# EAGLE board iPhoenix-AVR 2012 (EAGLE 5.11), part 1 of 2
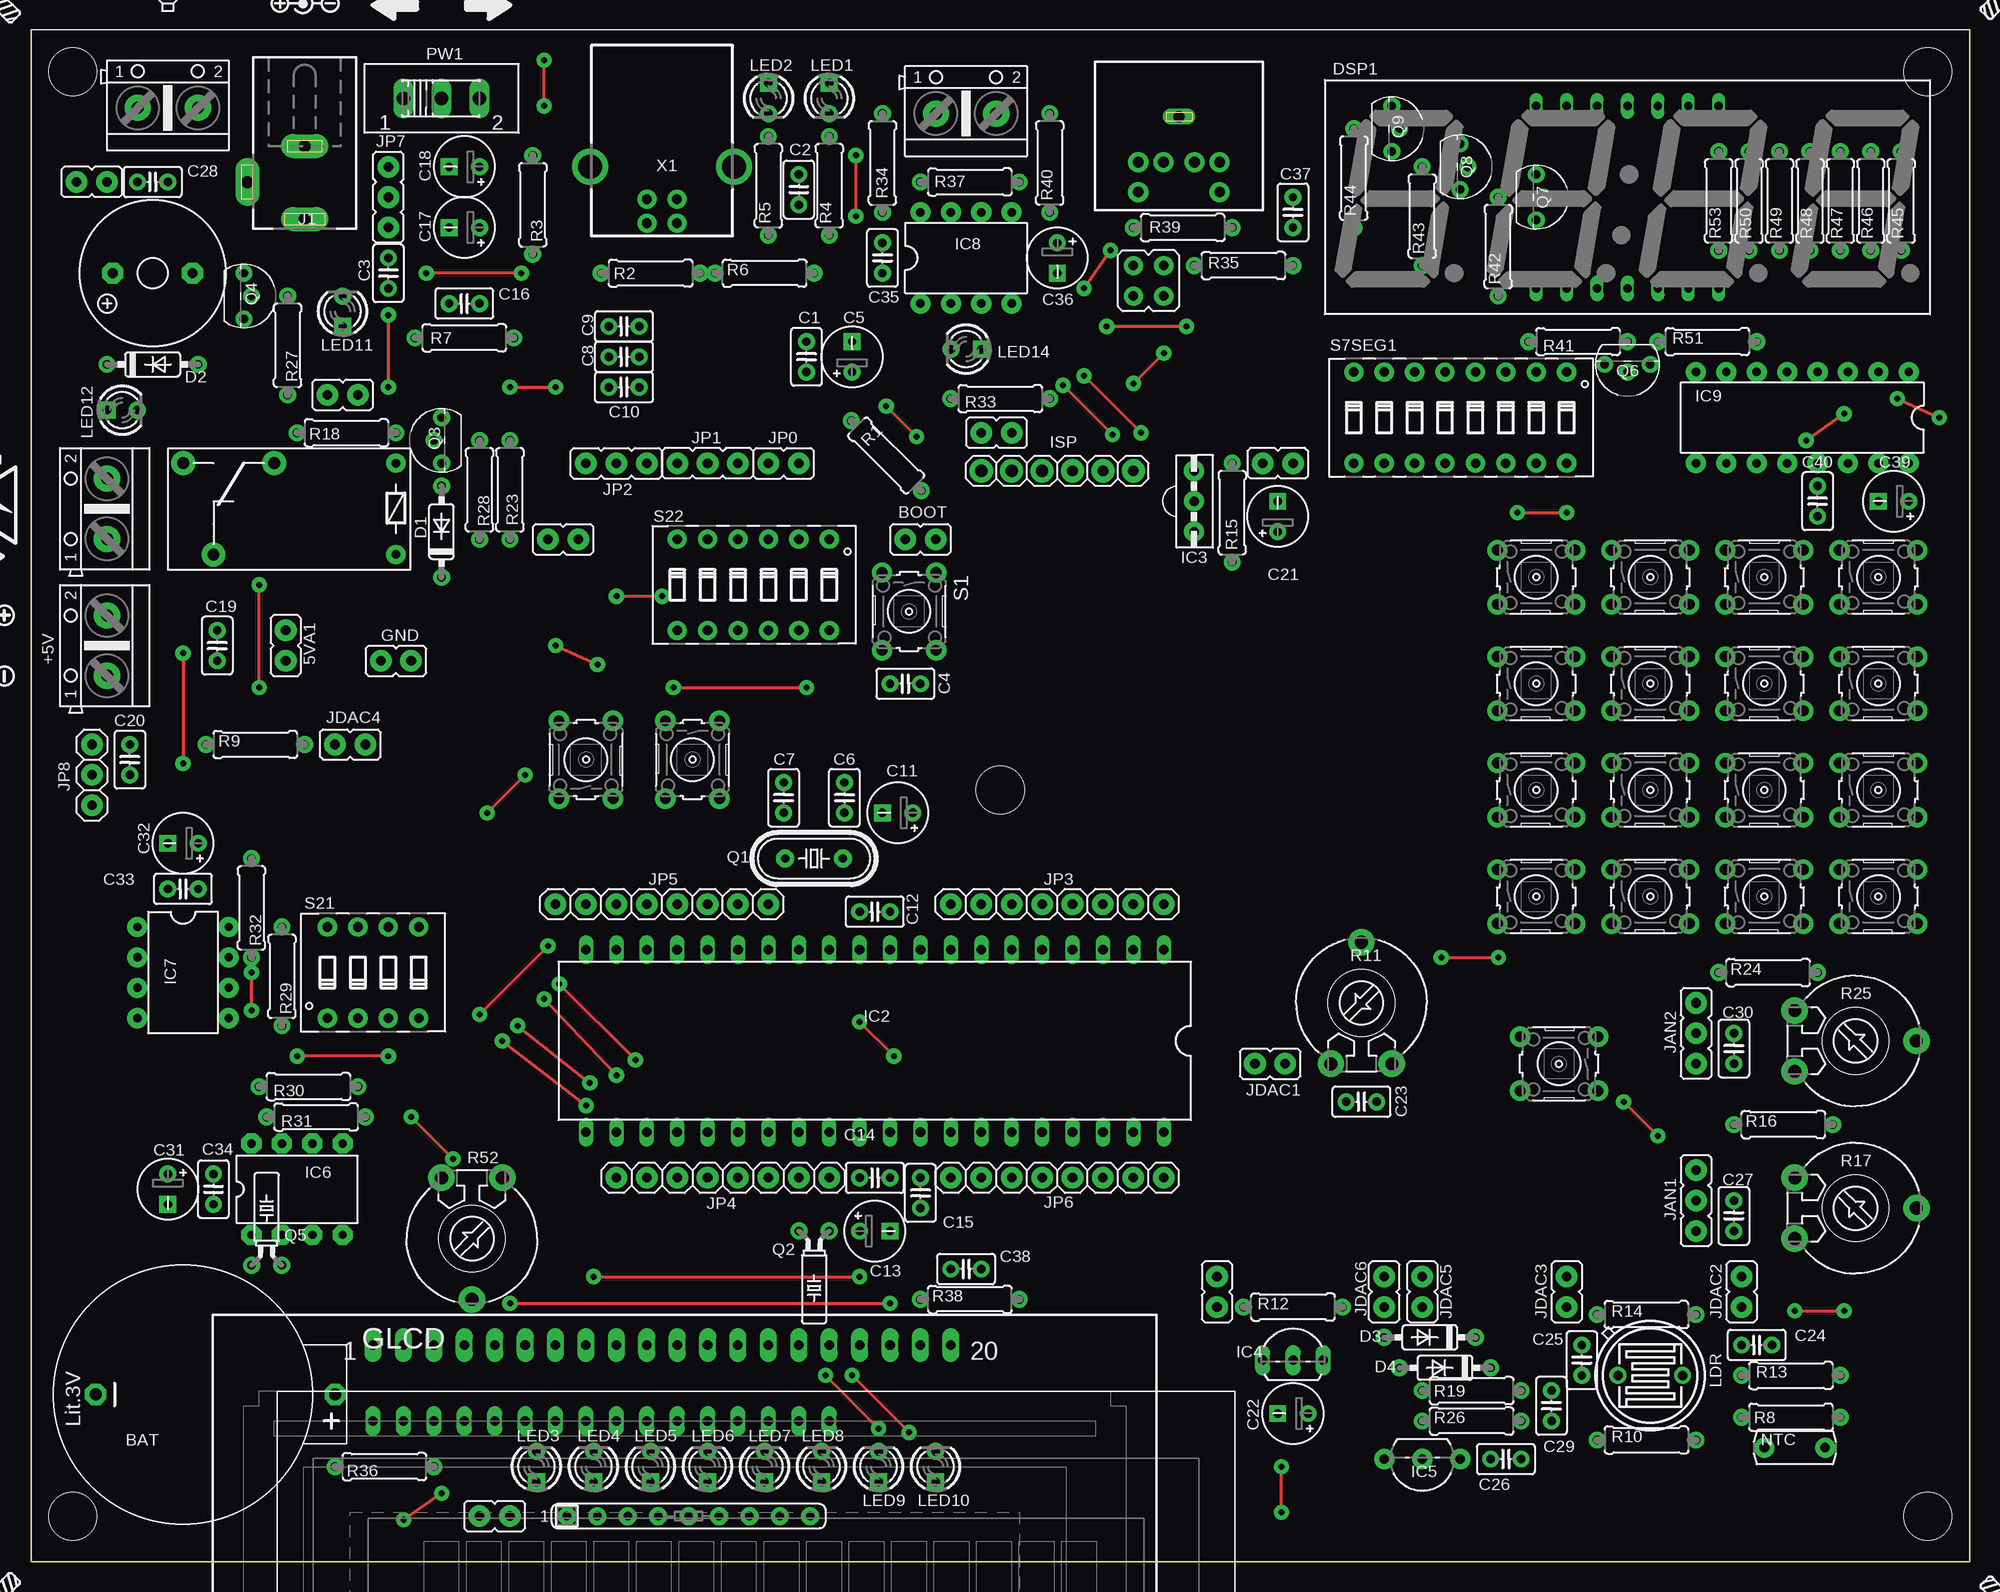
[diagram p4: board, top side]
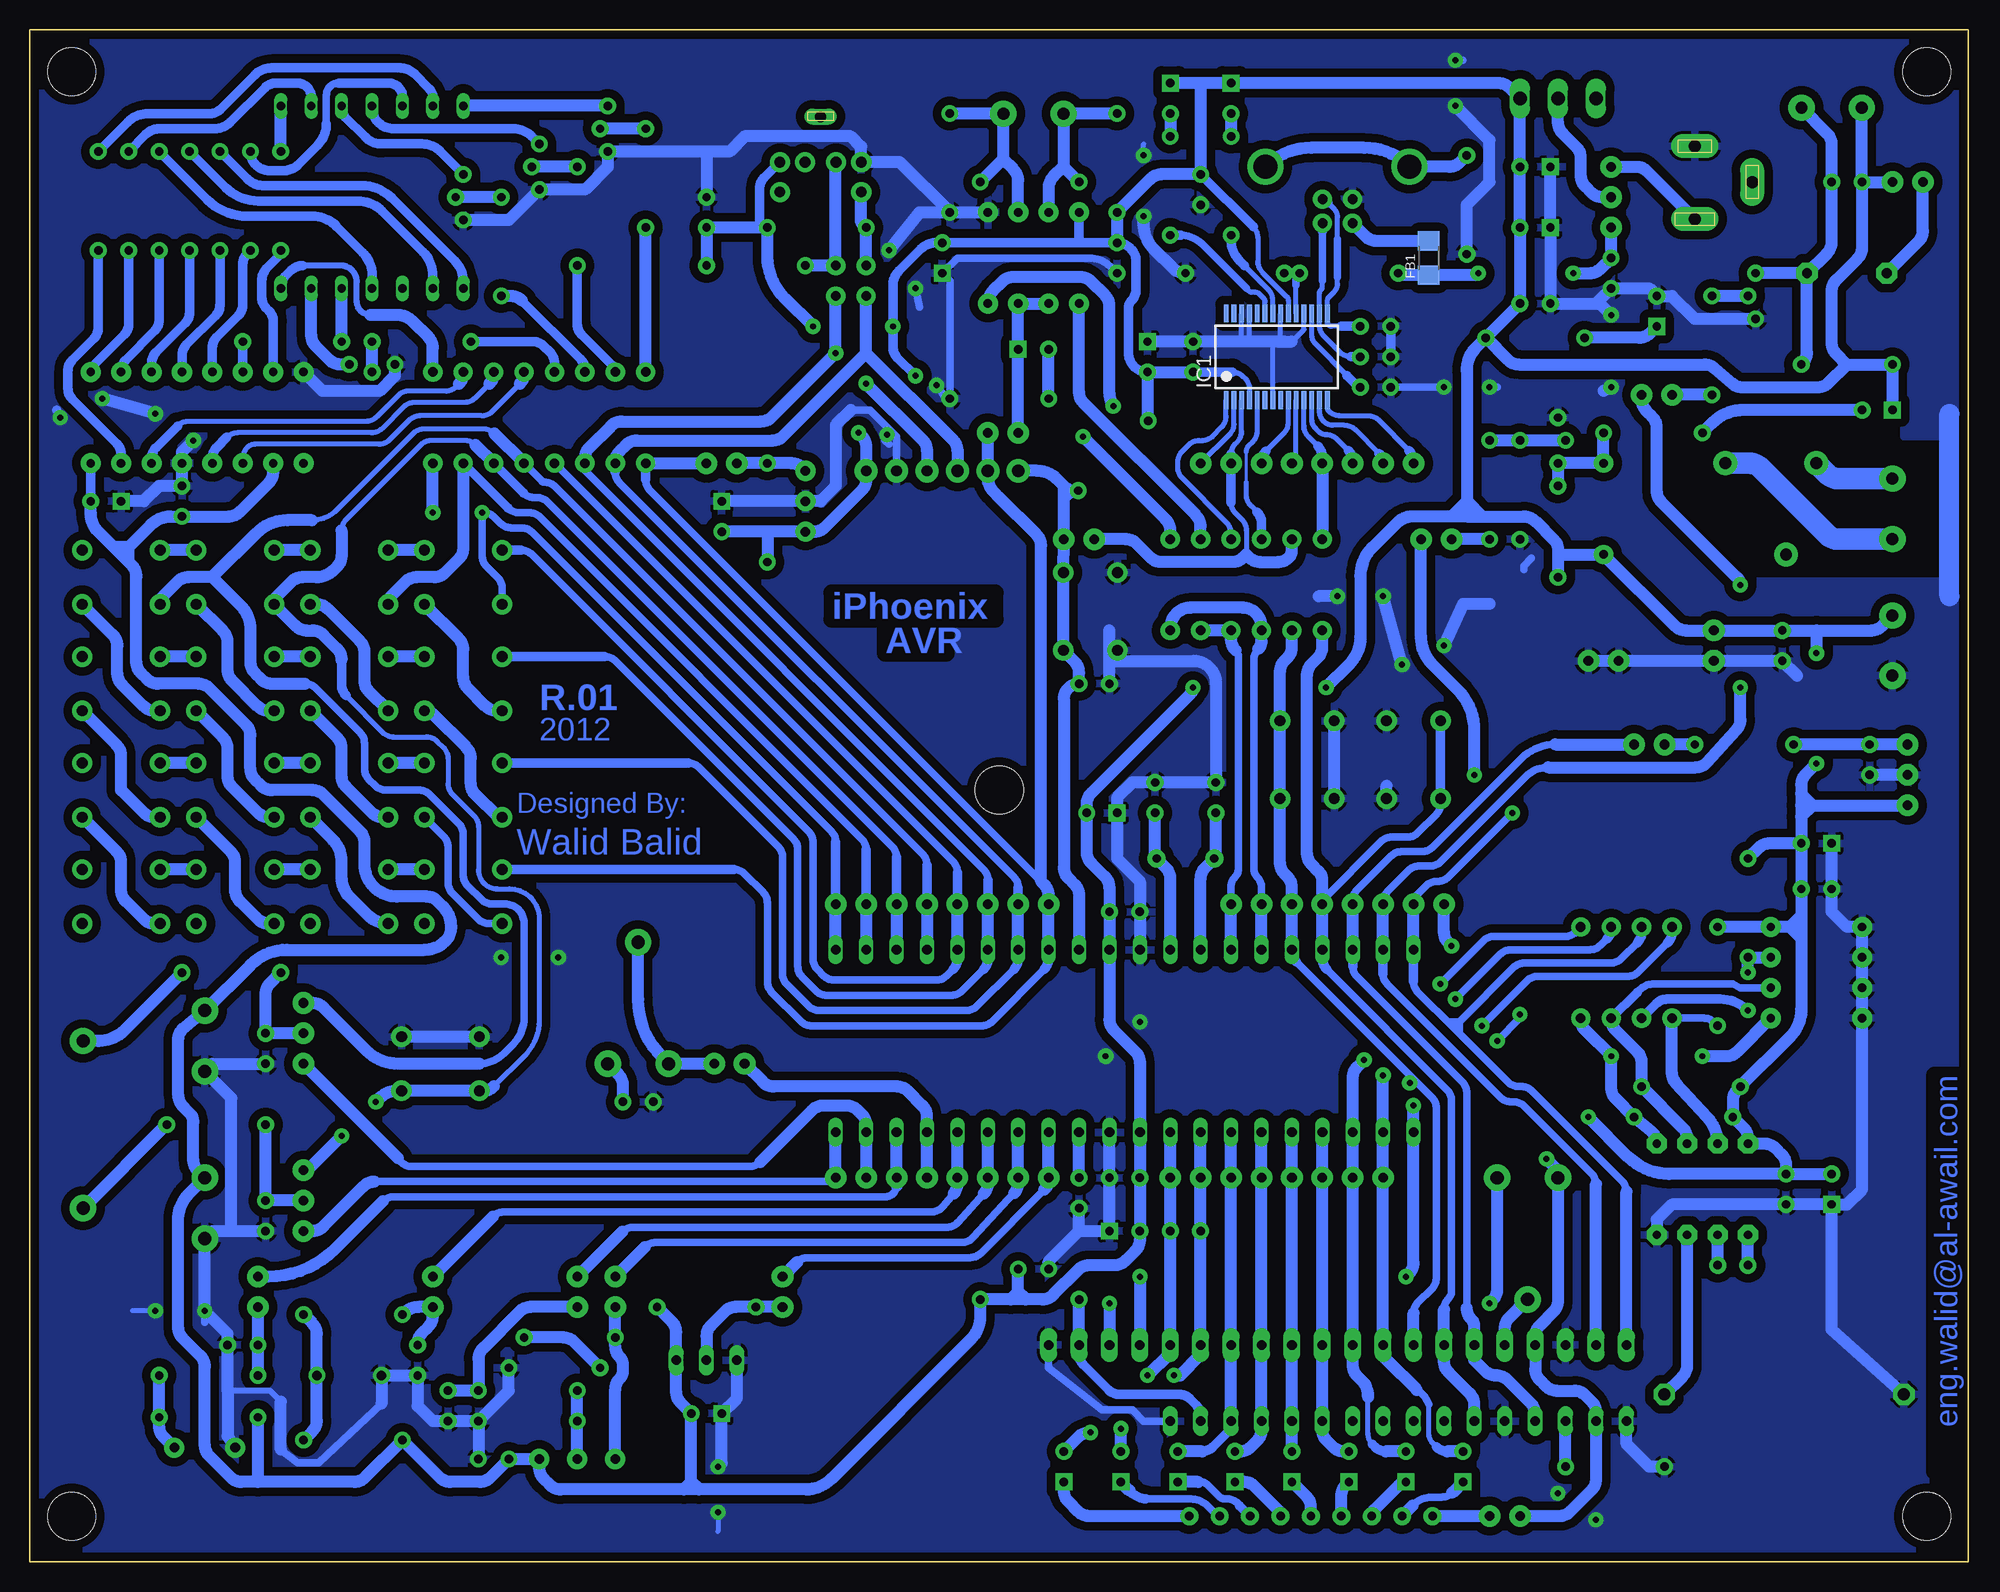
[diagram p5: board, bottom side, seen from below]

Size 161.92 x 127.95 mm. Coordinates in mm from the lower left corner, seen from the top.
Outline: 0,0 0,127.95 161.92,127.95 161.92,0 0,0
Copper layers (1*16): Top 0.035mm / dielectric 1.5mm / Bottom 0.035mm
Design rules "DVK2011 *": minimum track width 16mil, minimum drill 0.5mm, track to track 12mil, track to pad 12mil, pad to pad 12mil, via to via 12mil, smd to smd 12mil, copper to edge 1mil, drill to drill 12mil, minimum pad ring 8mil, minimum via ring 8mil, stop-mask expansion 4mil, vias tented up to drill 0.5mm, thermal gap 10mil
Holes 4 mm at 3.49,3.81 158.43,3.81 3.49,124.46 158.43,124.46 80.96,64.45

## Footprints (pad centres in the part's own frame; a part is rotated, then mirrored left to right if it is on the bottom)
JP1 = drill 0.8 pad 1.8 round: 1 0,-1.27; 2 0,1.27
AK500/2 = drill 1 pad 2.184 round: 1 -2.515,0; 2 2.515,0
BATT = drill 1 pad 1.778 octagon: + 0,10.16; - 0,-9.842
C025-025X050 = drill 0.7 pad 1.4 round: 1 -1.27,0; 2 1.27,0
E2,5-5 = drill 0.7 pad 1.4 round: + -1.27,0 | drill 0.7 pad 1.4 square: - 1.27,0
DO35-7 = drill 0.7 pad 1.4 round: A 3.81,0; C -3.81,0
F512SRWBT14 = drill 0.7 long: 1 -7.62,-6.35; 2 -5.08,-6.35; 3 -2.54,-6.35; 4 0,-6.35; 5 2.54,-6.35; 6 5.08,-6.35; 7 7.62,-6.35; 8 7.62,8.89; 9 5.08,8.89; 10 2.54,8.89; 11 0,8.89; 12 -2.54,8.89; 13 -5.08,8.89; 14 -7.62,8.89
R1206 = smd 1.6 x 1.803: 1 -1.422,0; 2 1.422,0
GDM12864B = drill 0.8 pad 1.422 long: 1 -26.034,33.019; 2 -23.494,33.019; 3 -20.954,33.019; 4 -18.414,33.019; 5 -15.874,33.019; 6 -13.334,33.019; 7 -10.794,33.019; 8 -8.254,33.019; 9 -5.714,33.019; 10 -3.174,33.019; 11 -0.634,33.019; 12 1.906,33.019; 13 4.446,33.019; 14 6.986,33.019; 15 9.526,33.019; 16 12.066,33.019; 17 14.606,33.019; 18 17.146,33.019; 19 19.686,33.019; 20 22.226,33.019
SSOP28 = smd 0.4 x 1.5: 1 -4.225,-3.625; 2 -3.575,-3.625; 3 -2.925,-3.625; 4 -2.275,-3.625; 5 -1.625,-3.625; 6 -0.975,-3.625; 7 -0.325,-3.625; 8 0.325,-3.625; 9 0.975,-3.625; 10 1.625,-3.625; 11 2.275,-3.625; 12 2.925,-3.625; 13 3.575,-3.625; 14 4.225,-3.625; 15 4.225,3.625; 16 3.575,3.625; 17 2.925,3.625; 18 2.275,3.625; 19 1.625,3.625; 20 0.975,3.625; 21 0.325,3.625; 22 -0.325,3.625; 23 -0.975,3.625; 24 -1.625,3.625; 25 -2.275,3.625; 26 -2.925,3.625; 27 -3.575,3.625; 28 -4.225,3.625
DIL40 = drill 0.813 long: 1 -24.13,-7.62; 2 -21.59,-7.62; 3 -19.05,-7.62; 4 -16.51,-7.62; 5 -13.97,-7.62; 6 -11.43,-7.62; 7 -8.89,-7.62; 8 -6.35,-7.62; 9 -3.81,-7.62; 10 -1.27,-7.62; 11 1.27,-7.62; 12 3.81,-7.62; 13 6.35,-7.62; 14 8.89,-7.62; 15 11.43,-7.62; 16 13.97,-7.62; 17 16.51,-7.62; 18 19.05,-7.62; 19 21.59,-7.62; 20 24.13,-7.62; 21 24.13,7.62; 22 21.59,7.62; 23 19.05,7.62; 24 16.51,7.62; 25 13.97,7.62; 26 11.43,7.62; 27 8.89,7.62; 28 6.35,7.62; 29 3.81,7.62; 30 1.27,7.62; 31 -1.27,7.62; 32 -3.81,7.62; 33 -6.35,7.62; 34 -8.89,7.62; 35 -11.43,7.62; 36 -13.97,7.62; 37 -16.51,7.62; 38 -19.05,7.62; 39 -21.59,7.62; 40 -24.13,7.62
IR-RECEIVER = drill 0.8 pad 1.676 round: GND 0,0; OUT 2.54,0; VCC -2.54,0
TO92L = drill 0.8 pad 1.27 long: 1 2.54,0; 2 0,0; 3 -2.54,0
LM35 = drill 0.8 pad 1.676 round: 1 3.175,0; 2 0,0; 3 -3.175,0
DIL8O = drill 0.7 pad 1.676 octagon: 1 -3.81,-3.81; 2 -1.27,-3.81; 3 1.27,-3.81; 4 3.81,-3.81; 5 3.81,3.81; 6 1.27,3.81; 7 -1.27,3.81; 8 -3.81,3.81
DIL8R = drill 0.7 pad 1.676 round: 1 -3.81,-3.81; 2 -1.27,-3.81; 3 1.27,-3.81; 4 3.81,-3.81; 5 3.81,3.81; 6 1.27,3.81; 7 -1.27,3.81; 8 -3.81,3.81
DIL16R = drill 0.7 pad 1.676 round: 1 -8.89,-3.81; 2 -6.35,-3.81; 3 -3.81,-3.81; 4 -1.27,-3.81; 5 1.27,-3.81; 6 3.81,-3.81; 7 6.35,-3.81; 8 8.89,-3.81; 9 8.89,3.81; 10 6.35,3.81; 11 3.81,3.81; 12 1.27,3.81; 13 -1.27,3.81; 14 -3.81,3.81; 15 -6.35,3.81; 16 -8.89,3.81
1X06 = drill 0.9 pad 1.93 round: 1 -6.35,0; 2 -3.81,0; 3 -1.27,0 | drill 1.016 pad 1.93 round: 4 1.27,0; 5 3.81,0; 6 6.35,0
DCJ0202 = drill 1 pad 2 long: 1 0,3.1; 2 4.8,0; 3 0,-3
JP2 = drill 0.8 pad 1.8 round: 1 -2.54,0; 2 0,0; 3 2.54,0
1X08 = drill 0.8 pad 1.8 round: 1 -8.89,0; 2 -6.35,0; 3 -3.81,0; 4 -1.27,0; 5 1.27,0; 6 3.81,0; 7 6.35,0; 8 8.89,0
1X03 = drill 0.8 pad 1.8 round: 1 -2.54,0; 2 0,0; 3 2.54,0
JP2Q = drill 0.8 pad 1.6 round: 1 -1.27,-1.27; 2 -1.27,1.27; 3 1.27,-1.27; 4 1.27,1.27
G5Q = drill 0.7 pad 1.6 round: 1 -4.445,5.08; 2 -4.445,-2.54 | drill 1 pad 2 round: C 10.795,5.08; O 13.335,-2.54; P 5.715,-2.54
DMC-162C = drill 0.8 pad 1.27 long: 1 8,33.5; 2 10.54,33.5; 3 13.08,33.5; 4 15.62,33.5; 5 18.16,33.5; 6 20.7,33.5; 7 23.24,33.5; 8 25.78,33.5; 9 28.32,33.5; 10 30.86,33.5; 11 33.4,33.5; 12 35.94,33.5; 13 38.48,33.5; 14 41.02,33.5; 15 43.56,33.5; 16 46.1,33.5
TO-5_V10 = drill 0.8 pad 1.4 round: 1 -2.7,0; 2 2.7,0
LED3MM = drill 0.7 pad 1.422 square: A -1.27,0 | drill 0.7 pad 1.422 round: K 1.27,0
N640W = drill 0.8 pad 1.676 round: 1 -2.54,0; 2 2.54,0
PS2-CON = drill 0.9 pad 1.676 round: 1 1.3,8.5; 2 -1.3,8.5; 3 3.4,8.5; 4 -3.4,8.5; 5 3.4,11; 6 -3.4,11 | drill 0.9 long: M 0,4.7
230SB = drill 1.118 long: 1 -3.175,0; 2 0,0; 3 3.175,0
HC49 = drill 0.7 pad 1.5 round: 1 -2.413,0; 2 2.413,0
TC26 = drill 0.7 pad 1.422 round: 1 -1.27,-5.08; 2 1.27,-5.08
TO92 = drill 0.7 pad 1.4 round: 1 1.905,0; 2 0,0.635; 3 -1.905,0
0207/8 = drill 0.7 pad 1.4 round: 1 -3.81,0; 2 4.445,0
POT = drill 1.1 pad 2.2 round: A -2.54,-5.08; E 2.54,-5.08; S 0,5.08
SIL9 = drill 0.7 pad 1.5 round: 1 -10.16,0; 2 -7.62,0; 3 -5.08,0; 4 -2.54,0; 5 0,0; 6 2.54,0; 7 5.08,0; 8 7.62,0; 9 10.16,0
B3F-10XX = drill 0.9 pad 1.7 round: 1 -3.251,2.261; 2 3.251,2.261; 3 -3.251,-2.261; 4 3.251,-2.261
DIP08YL = drill 0.8 pad 1.6 round: 1 -8.89,-3.81; 2 -6.35,-3.81; 3 -3.81,-3.81; 4 -1.27,-3.81; 5 1.27,-3.81; 6 3.81,-3.81; 7 6.35,-3.81; 8 8.89,-3.81; 9 8.89,3.81; 10 6.35,3.81; 11 3.81,3.81; 12 1.27,3.81; 13 -1.27,3.81; 14 -3.81,3.81; 15 -6.35,3.81; 16 -8.89,3.81
DIP04YL = drill 0.8 pad 1.6 round: 1 -3.81,-3.81; 2 -1.27,-3.81; 3 1.27,-3.81; 4 3.81,-3.81; 5 3.81,3.81; 6 1.27,3.81; 7 -1.27,3.81; 8 -3.81,3.81
DIP06YL = drill 0.8 pad 1.6 round: 1 -6.35,-3.81; 2 -3.81,-3.81; 3 -1.27,-3.81; 4 1.27,-3.81; 5 3.81,-3.81; 6 6.35,-3.81; 7 6.35,3.81; 8 3.81,3.81; 9 1.27,3.81; 10 -1.27,3.81; 11 -3.81,3.81; 12 -6.35,3.81
F/TAT = drill 0.8 pad 1.778 octagon: + 3.334,0; - -3.334,0
PN61729-S = drill 0.8 pad 1.6 round: 1 1.25,4.71; 2 -1.25,4.71; 3 -1.25,2.71; 4 1.25,2.71 | drill 2 pad 2.9 round: S1 -6.02,0; S2 6.02,0

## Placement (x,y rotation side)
5VA1  [JP1]  21.27,76.52 0 top
+5V  [AK500/2]  6.35,76.52 90 top
BAT  CR2032  [BATT]  15.24,13.97 270 top
BOOT  [JP1]  74.29,85.41 90 top
C1  100nF  [C025-025X050]  64.77,100.65 270 top
C2  100nF  [C025-025X050]  64.13,114.62 90 top
C3  100nF  [C025-025X050]  29.84,107.63 270 top
C4  1nF  [C025-025X050]  73.02,73.34 0 top
C5  4.7uF  [E2,5-5]  68.58,100.65 90 top
C6  22pF  [C025-025X050]  67.94,63.82 90 top
C7  22pF  [C025-025X050]  62.86,63.82 90 top
C8  47pF  [C025-025X050]  49.53,100.65 180 top
C9  47pF  [C025-025X050]  49.53,103.19 180 top
C10  100nF  [C025-025X050]  49.53,98.11 180 top
C11  4.7uF  [E2,5-5]  72.39,62.55 180 top
C12  100nF  [C025-025X050]  70.48,54.29 180 top
C13  4.7uF  [E2,5-5]  70.48,27.62 0 top
C14  100nF  [C025-025X050]  70.48,32.07 0 top
C15  100nF  [C025-025X050]  74.29,30.8 270 top
C16  100nF  [C025-025X050]  36.19,105.09 180 top
C17  100uF  [E2,5-5]  36.19,111.44 180 top
C18  10uF  [E2,5-5]  36.19,116.52 180 top
C19  100nF  [C025-025X050]  15.56,76.52 270 top
C20  100nF  [C025-025X050]  8.25,66.99 270 top
C21  4.7uF  [E2,5-5]  104.14,87.31 90 top
C22  4.7uF  [E2,5-5]  105.41,12.38 180 top
C23  100nF  [C025-025X050]  111.12,38.42 180 top
C24  100nF  [C025-025X050]  144.14,18.1 180 top
C25  100nF  [C025-025X050]  129.54,16.83 270 top
C26  100nF  [C025-025X050]  123.19,8.57 0 top
C27  100nF  [C025-025X050]  142.24,28.89 90 top
C28  100nF  [C025-025X050]  10.16,115.25 0 top
C29  100nF  [C025-025X050]  127,13.02 270 top
C30  100nF  [C025-025X050]  142.24,42.86 90 top
C31  4.7uF  [E2,5-5]  11.43,31.11 270 top
C32  4.7uF  [E2,5-5]  12.7,60.01 180 top
C33  100nF  [C025-025X050]  12.7,56.2 180 top
C34  100nF  [C025-025X050]  15.24,31.11 90 top
C35  100nF  [C025-025X050]  71.12,108.9 270 top
C36  4.7uF  [E2,5-5]  85.72,108.9 270 top
C37  100nF  [C025-025X050]  105.41,112.71 90 top
C38  100nF  [C025-025X050]  78.1,24.45 0 top
C39  4.7uF  [E2,5-5]  155.57,88.58 180 top
C40  100nF  [C025-025X050]  149.22,88.58 270 top
D1  1N4148  [DO35-7]  34.29,86.04 90 top
D2  1N4148  [DO35-7]  10.16,100.01 0 top
D3  1N4148  [DO35-7]  116.84,18.73 180 top
D4  1N4148  [DO35-7]  118.11,16.19 180 top
DSP1  [F512SRWBT14]  133.35,112.71 0 top
FB1  [R1206]  45.08,108.9 90 bottom
GLCD  GDM12864B  [GDM12864B]  54.61,-14.92 0 top
GND  [JP1]  30.48,75.25 90 top
IC1  FT232RL  [SSOP28]  57.78,100.65 0 bottom
IC2  ATmega32  [DIL40]  70.48,43.5 180 top
IC3  CLRM-2038S  [IR-RECEIVER]  97.15,88.58 90 top
IC4  DS18B20  [TO92L]  105.41,16.83 0 top
IC5  LM35DZ  [LM35]  116.2,8.57 0 top
IC6  DS1307  [DIL8O]  22.22,31.11 0 top
IC7  AT24C32  [DIL8R]  12.7,49.21 270 top
IC8  MAX485  [DIL8R]  78.1,108.9 0 top
IC9  M74HC595  [DIL16R]  147.95,95.57 180 top
ISP  [1X06]  85.72,91.12 180 top
J1  D-005, 2mm  [DCJ0202]  22.86,115.25 180 top
J1W  [JP1]  99.06,22.54 0 top
JAN1  [JP2]  139.06,30.16 90 top
JAN2  [JP2]  139.06,44.13 90 top
JBUZ  [JP1]  5.08,115.25 270 top
JDAC1  [JP1]  103.5,41.59 90 top
JDAC2  [JP1]  142.88,22.54 0 top
JDAC3  [JP1]  128.27,22.54 0 top
JDAC4  [JP1]  26.67,68.26 90 top
JDAC5  [JP1]  116.2,22.54 0 top
JDAC6  [JP1]  113.03,22.54 180 top
JLEDD  [JP1]  38.73,3.81 90 top
JP0  [JP1]  62.86,91.76 90 top
JP1  [JP2]  56.51,91.76 0 top
JP2  [JP2]  48.89,91.76 180 top
JP3  [1X08]  85.72,54.93 180 top
JP4  [1X08]  57.78,32.07 0 top
JP5  [1X08]  52.7,54.93 180 top
JP6  [1X08]  85.72,32.07 180 top
JP7  [JP2]  29.84,113.98 270 top
JP8  [1X03]  5.08,65.72 90 top
JP9  [JP1]  80.64,94.3 270 top
JPS  [JP2Q]  93.34,107 180 top
JRC5R  [JP1]  104.14,91.76 270 top
JRLY  [JP1]  44.45,85.41 90 top
JSPK  [JP1]  26.03,97.47 90 top
K1  G5Q-1-5V  [G5Q]  26.03,89.22 180 top
LCD  GDM1602  [DMC-162C]  20.58,-21.75 0 top
LDR  100K  [TO-5_V10]  135.25,15.56 180 top
LED1  Green  [LED3MM]  66.67,122.24 270 top
LED2  Green  [LED3MM]  61.59,122.24 270 top
LED3  [LED3MM]  42.23,7.94 90 top
LED4  [LED3MM]  46.99,7.94 90 top
LED5  [LED3MM]  51.75,7.94 90 top
LED6  [LED3MM]  56.51,7.94 90 top
LED7  [LED3MM]  61.28,7.94 90 top
LED8  [LED3MM]  66.04,7.94 90 top
LED9  [LED3MM]  70.8,7.94 90 top
LED10  [LED3MM]  75.56,7.94 90 top
LED11  Green  [LED3MM]  26.03,104.46 90 top
LED12  Green  [LED3MM]  7.62,96.2 0 top
LED14  Green  [LED3MM]  78.1,101.28 180 top
NTC  10k  [N640W]  147.32,9.52 0 top
PS1  DIN-6  [PS2-CON]  95.88,125.41 180 top
PW1  [230SB]  34.29,122.24 0 top
Q1  16MHz  [HC49]  65.4,58.74 180 top
Q2  32K  [TC26]  65.4,22.54 180 top
Q3  BC337  [TO92]  34.29,93.66 90 top
Q4  BC337  [TO92]  17.78,105.73 270 top
Q5  32KHz  [TC26]  19.68,29.84 0 top
Q6  BC337  [TO92]  133.35,100.01 180 top
Q7  BC337  [TO92]  125.73,113.98 270 top
Q8  BC337  [TO92]  119.38,116.52 270 top
Q9  BC337  [TO92]  113.66,119.7 270 top
QR1  DG306-5.0-02P  [AK500/2]  6.35,87.95 90 top
R1  10K  [0207/8]  71.66,92.17 135 top
R2  4K7  [0207/8]  52.07,107.63 180 top
R3  100K  [0207/8]  41.91,113.66 270 top
R4  1K  [0207/8]  66.67,114.62 90 top
R5  1K  [0207/8]  61.59,114.62 90 top
R6  10K  [0207/8]  60.96,107.63 0 top
R7  1K  [0207/8]  35.88,102.23 0 top
R8  10K  [0207/8]  147.32,12.06 180 top
R9  10K  [0207/8]  19.05,68.26 180 top
R10  10K  [0207/8]  135.25,10.16 180 top
R11  10K  [POT]  111.12,46.67 0 top
R12  4K7  [0207/8]  105.09,21.27 0 top
R13  100  [0207/8]  147.32,15.56 180 top
R14  100  [0207/8]  135.25,20.64 180 top
R15  10K  [0207/8]  100.33,87.95 270 top
R16  1K  [0207/8]  146.05,36.51 0 top
R17  10K  [POT]  152.4,29.53 270 top
R18  1K  [0207/8]  26.67,94.3 180 top
R19  100  [0207/8]  120.01,14.29 0 top
R23  1K  [0207/8]  40,89.22 90 top
R24  1K  [0207/8]  144.78,49.21 0 top
R25  10K  [POT]  152.4,43.5 270 top
R26  20K  [0207/8]  120.01,11.75 0 top
R27  1K  [0207/8]  21.43,101.28 90 top
R28  1K  [0207/8]  37.46,89.22 90 top
R29  4K7  [0207/8]  20.95,48.58 90 top
R30  4K7  [0207/8]  23.49,39.69 180 top
R31  4K7  [0207/8]  24.13,37.15 180 top
R32  10K  [0207/8]  18.41,54.29 90 top
R33  1K  [0207/8]  81.28,97.16 180 top
R34  1K  [0207/8]  71.12,117.16 270 top
R35  4K7  [0207/8]  100.96,108.27 0 top
R36  2K  [0207/8]  29.21,7.94 0 top
R37  120  [0207/8]  78.74,115.25 180 top
R38  10  [0207/8]  78.1,21.91 0 top
R39  4K7  [0207/8]  96.52,111.44 180 top
R40  1K  [0207/8]  85.09,116.52 90 top
R41  4K7  [0207/8]  129.54,101.92 180 top
R42  4K7  [0207/8]  122.55,110.17 270 top
R43  4K7  [0207/8]  116.2,112.71 270 top
R44  4K7  [0207/8]  110.49,115.89 270 top
R45  100  [0207/8]  156.21,113.35 90 top
R46  100  [0207/8]  153.67,113.35 90 top
R47  100  [0207/8]  151.13,113.35 90 top
R48  100  [0207/8]  148.59,113.35 90 top
R49  100  [0207/8]  146.05,113.35 90 top
R50  100  [0207/8]  143.51,113.35 90 top
R51  100  [0207/8]  140.33,101.92 180 top
R52  10K  [POT]  36.83,26.99 180 top
R53  100  [0207/8]  140.97,113.35 90 top
RN1  4K7  [SIL9]  54.93,3.81 0 top
RS1  DG306-5.0-02P  [AK500/2]  78.1,120.97 0 top
S1  [B3F-10XX]  73.34,79.38 270 top
S2  [B3F-10XX]  125.73,82.23 0 top
S3  [B3F-10XX]  135.25,82.23 0 top
S4  [B3F-10XX]  144.78,82.23 0 top
S5  [B3F-10XX]  154.3,82.23 0 top
S6  [B3F-10XX]  125.73,73.34 0 top
S7  [B3F-10XX]  135.25,73.34 0 top
S7SEG1  [DIP08YL]  119.38,95.57 180 top
S8  [B3F-10XX]  144.78,73.34 0 top
S9  [B3F-10XX]  154.3,73.34 0 top
S10  [B3F-10XX]  125.73,64.45 0 top
S11  [B3F-10XX]  135.25,64.45 0 top
S12  [B3F-10XX]  144.78,64.45 0 top
S13  [B3F-10XX]  154.3,64.45 0 top
S14  [B3F-10XX]  125.73,55.56 0 top
S15  [B3F-10XX]  135.25,55.56 0 top
S16  [B3F-10XX]  144.78,55.56 0 top
S17  [B3F-10XX]  154.3,55.56 0 top
S18  [B3F-10XX]  55.24,66.99 270 top
S19  [B3F-10XX]  46.35,66.99 90 top
S20  [B3F-10XX]  127.63,41.59 180 top
S21  [DIP04YL]  28.57,49.21 0 top
S22  [DIP06YL]  60.32,81.6 180 top
SG1  BM1290-0520-4202-09B04  [F/TAT]  10.16,107.63 180 top
SPK  DG306-5.0-02P  [AK500/2]  11.43,121.44 0 top
U$1  [ICON_POSITIVE_CENTER-M]  22.7,130.17 0 top
U$3  [ICON_VOLTAGE-S]  not placed on the board
U$4  [ICON_SPEAKER]  11.43,130.17 90 top
U$5  [ICON_MSCREW-S]  -2.86,130.49 45 top
U$6  [ICON_MSCREW-S]  164.78,130.81 315 top
U$7  [ICON_MSCREW-S]  not placed on the board
U$8  [ICON_MSCREW-S]  -2.86,-2.86 135 top
U$9  [ICON_PLUS]  -2.22,79.06 0 top
U$10  [ICON_MINUS]  -2.22,73.98 90 top
U$18  [ICON_ARROW-S]  38.26,130.02 270 top
U$19  [ICON_ARROW-S]  30.32,130.02 90 top
U$27  [ICON_ARROW-S]  not placed on the board
U$28  [ICON_ARROW-S]  not placed on the board
X1  USB-M-C  [PN61729-S]  52.7,116.52 180 top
